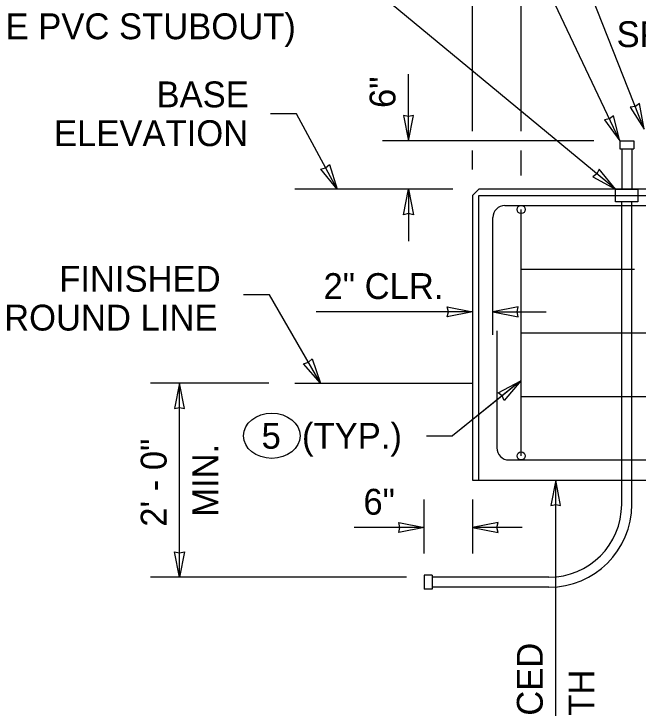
# Model space of a CAD drawing. Extents: x 99888 to 103177, y 100000 to 102076.
# Drawn here: x 101256.4 to 101642.5, y 100934.2 to 101363.8 of the extents above; entities that cross this region are included whole.
import ezdxf

# ---------------------------------------------------------------- set-up
doc = ezdxf.new("R2010")
doc.units = 0
for name, color, linetype in [('Level 10', 7, 'Continuous'), ('Level 15', 7, 'Continuous'), ('Level 2', 7, 'Continuous'), ('Level 20', 7, 'Continuous'), ('Level 36', 7, 'Continuous'), ('Level 6', 7, 'Continuous')]:
    doc.layers.add(name, color=color, linetype=linetype)

msp = doc.modelspace()

# ---------------------------------------------------------------- linework, layer by layer
at = {"layer": 'Level 10'}
for p, q in [((101560.13, 101245.28), (102060.17, 101245.28)), ((101560.13, 101245.28), (102060.17, 101245.28)), ((101570.13, 101090.28), (101570.13, 101242.78)), ((101552.63, 101165.3), (101552.63, 101237.78)), ((101570.13, 101205.9), (101640.13, 101205.9)), ((101570.13, 101205.9), (101640.13, 101205.9)), ((101555.13, 101167.78), (101555.13, 101095.28)), ((101570.13, 101166.53), (101750.13, 101166.53)), ((101570.13, 101127.15), (101750.13, 101127.15)), ((101562.63, 101087.78), (102057.67, 101087.78))]:
    msp.add_line(p, q, dxfattribs=at)
for centre, start, end in [((101560.13, 101237.78), 90, 180), ((101560.13, 101237.78), 90, 180), ((101562.63, 101095.28), 180, 270), ((101562.63, 101095.28), 180, 270)]:
    msp.add_arc(centre, 7.5, start, end, dxfattribs=at)
at = {"layer": 'Level 15'}
for p, q in [((101646.23, 101292.52), (101519.17, 101615.06)), ((101631.06, 101285.28), (101519.17, 101521.98)), ((101628.49, 101255.3), (101463.21, 101392.16)), ((101540.13, 101330.19), (101540.13, 101383.28)), ((101570.13, 101350.07), (101570.13, 101383.28)), ((101570.13, 101306.8), (101570.13, 101350.07)), ((101570.13, 101306.8), (101570.13, 101350.07)), ((101540.13, 101291.28), (101540.13, 101332.3)), ((101500.4, 101285.28), (101500.4, 101326.59)), ((101500.4, 101285.28), (101500.4, 101326.59)), ((101540.13, 101291.28), (101540.13, 101318.19)), ((101570.13, 101291.28), (101570.13, 101306.8)), ((101431.2, 101302.02), (101415.2, 101302.02)), ((101456.33, 101255.28), (101431.2, 101302.02)), ((101570.13, 101291.28), (101570.13, 101294.8)), ((101582.35, 101285.28), (101484.4, 101285.28)), ((101582.35, 101285.28), (101484.4, 101285.28)), ((101615.06, 101285.28), (101582.35, 101285.28)), ((101615.06, 101285.28), (101597.74, 101285.28)), ((101540.13, 101267.53), (101540.13, 101279.28)), ((101540.13, 101267.53), (101540.13, 101279.28)), ((101570.13, 101263.78), (101570.13, 101279.28)), ((101570.13, 101263.78), (101570.13, 101279.28)), ((101527.88, 101255.28), (101430.09, 101255.28)), ((101527.88, 101255.28), (101430.09, 101255.28)), ((101500.4, 101255.28), (101500.4, 101223.28)), ((101500.4, 101255.28), (101500.4, 101223.28)), ((101414.46, 101189.97), (101398.46, 101189.97)), ((101414.46, 101189.97), (101398.46, 101189.97)), ((101446.09, 101135.28), (101414.46, 101189.97)), ((101446.09, 101135.28), (101414.46, 101189.97)), ((101540.13, 101179.4), (101443.35, 101179.4)), ((101540.13, 101179.4), (101443.35, 101179.4)), ((101552.6, 101179.4), (101579.27, 101179.4)), ((101552.6, 101179.4), (101585.56, 101179.4)), ((101570, 101136.86), (101527.57, 101102.75)), ((101414.09, 101135.28), (101340.87, 101135.28)), ((101358.87, 101015.28), (101358.87, 101135.28)), ((101358.87, 101015.28), (101358.87, 101135.28)), ((101430.09, 101135.28), (101540.13, 101135.28)), ((101430.09, 101135.28), (101540.13, 101135.28)), ((101568.5, 101135.65), (101527.57, 101102.75)), ((101511.57, 101102.75), (101527.57, 101102.75)), ((101511.57, 101102.75), (101527.57, 101102.75)), ((101591.47, 100563.54), (101591.47, 101075.28)), ((101591.47, 100563.54), (101591.47, 101075.28)), ((101510.13, 101029.86), (101510.13, 101063.28)), ((101510.13, 101029.86), (101510.13, 101063.28)), ((101540.13, 101063.28), (101540.13, 101029.94)), ((101540.13, 101063.28), (101540.13, 101029.94)), ((101510.13, 101045.94), (101466.8, 101045.94)), ((101510.13, 101045.94), (101466.8, 101045.94)), ((101566.8, 101045.94), (101540.13, 101045.94)), ((101570.66, 101045.94), (101540.13, 101045.94)), ((101499.13, 101015.28), (101340.87, 101015.28))]:
    msp.add_line(p, q, dxfattribs=at)
for points in [[(101646.23, 101292.52), (101643.38, 101308.29), (101640.77, 101306.49), (101637.64, 101306.04)], [(101500.4, 101285.28), (101503.48, 101301), (101500.4, 101300.27), (101497.31, 101301)], [(101500.4, 101285.28), (101503.48, 101301), (101500.4, 101300.27), (101497.31, 101301)], [(101631.06, 101285.28), (101627.25, 101300.84), (101624.76, 101298.88), (101621.65, 101298.25)], [(101456.33, 101255.28), (101446.15, 101267.65), (101449.21, 101268.48), (101451.58, 101270.58)], [(101628.49, 101255.3), (101618.35, 101267.71), (101616.94, 101264.87), (101614.41, 101262.96)], [(101500.4, 101255.28), (101503.48, 101239.55), (101500.4, 101240.28), (101497.31, 101239.55)], [(101500.4, 101255.28), (101503.48, 101239.55), (101500.4, 101240.28), (101497.31, 101239.55)], [(101540.13, 101179.4), (101524.41, 101176.32), (101525.14, 101179.4), (101524.41, 101182.49)], [(101540.13, 101179.4), (101524.41, 101176.32), (101525.14, 101179.4), (101524.41, 101182.49)], [(101552.6, 101179.4), (101568.33, 101176.32), (101567.6, 101179.4), (101568.33, 101182.49)], [(101552.6, 101179.4), (101568.33, 101176.32), (101567.6, 101179.4), (101568.33, 101182.49)], [(101446.09, 101135.28), (101435.55, 101147.35), (101438.59, 101148.26), (101440.9, 101150.44)], [(101570, 101136.86), (101559.68, 101124.61), (101558.31, 101127.47), (101555.81, 101129.42)], [(101358.87, 101135.28), (101355.79, 101119.55), (101358.87, 101120.28), (101361.95, 101119.55)], [(101358.87, 101135.28), (101355.79, 101119.55), (101358.87, 101120.28), (101361.95, 101119.55)], [(101591.47, 101075.28), (101588.38, 101059.55), (101591.47, 101060.28), (101594.55, 101059.55)], [(101591.47, 101075.28), (101588.38, 101059.55), (101591.47, 101060.28), (101594.55, 101059.55)], [(101510.13, 101045.94), (101494.41, 101042.86), (101495.14, 101045.94), (101494.41, 101049.03)], [(101510.13, 101045.94), (101494.41, 101042.86), (101495.14, 101045.94), (101494.41, 101049.03)], [(101540.13, 101045.94), (101555.86, 101042.86), (101555.13, 101045.94), (101555.86, 101049.03)], [(101540.13, 101045.94), (101555.86, 101042.86), (101555.13, 101045.94), (101555.86, 101049.03)], [(101358.87, 101015.28), (101355.79, 101031), (101358.87, 101030.27), (101361.95, 101031)]]:
    msp.add_lwpolyline(points, close=True, dxfattribs=at)
at = {"layer": 'Level 2'}
for p, q in [((101543.88, 101255.28), (101540.13, 101251.53)), ((101543.88, 101255.28), (101540.13, 101251.53)), ((102076.38, 101255.28), (101543.88, 101255.28)), ((101540.13, 101251.53), (101540.13, 101075.28)), ((101543.88, 101075.28), (101543.88, 101251.53)), ((101543.88, 101251.53), (102076.38, 101251.53)), ((101543.88, 101075.28), (101543.88, 101251.53)), ((101543.88, 101251.53), (102076.38, 101251.53)), ((101540.13, 101075.28), (101720.13, 101075.28))]:
    msp.add_line(p, q, dxfattribs=at)
at = {"layer": 'Level 20'}
msp.add_ellipse((101415.89, 101102.76), major_axis=(-17.5, 0), ratio=0.8, dxfattribs=at)
at = {"layer": 'Level 36'}
for centre in [(101570.13, 101242.78), (101570.13, 101242.78), (101570.13, 101090.28), (101570.13, 101090.28)]:
    msp.add_circle(centre, 2.5, dxfattribs=at)
at = {"layer": 'Level 6'}
for p, q in [((101631.06, 101285.28), (101639.81, 101285.28)), ((101631.06, 101285.28), (101631.06, 101280.28)), ((101631.06, 101285.28), (101639.81, 101285.28)), ((101631.06, 101285.28), (101631.06, 101280.28)), ((101639.81, 101285.28), (101639.81, 101280.28)), ((101639.81, 101285.28), (101639.81, 101280.28)), ((101631.06, 101280.28), (101639.81, 101280.28)), ((101631.06, 101280.28), (101639.81, 101280.28)), ((101632.31, 101280.28), (101632.31, 101255.28)), ((101632.31, 101280.28), (101632.31, 101255.28)), ((101638.56, 101280.28), (101638.56, 101255.28)), ((101638.56, 101280.28), (101638.56, 101255.28)), ((101632.31, 101075.28), (101632.31, 101247.56)), ((101632.31, 101075.28), (101632.31, 101247.56)), ((101638.56, 101075.28), (101638.56, 101247.56)), ((101638.56, 101075.28), (101638.56, 101247.56)), ((101632.31, 101060.28), (101632.31, 101075.28)), ((101632.31, 101060.28), (101632.31, 101075.28)), ((101638.56, 101060.28), (101638.56, 101075.28)), ((101638.56, 101060.28), (101638.56, 101075.28)), ((101510.13, 101016.53), (101510.13, 101007.78)), ((101515.13, 101016.53), (101510.13, 101016.53)), ((101510.13, 101016.53), (101510.13, 101007.78)), ((101515.13, 101016.53), (101510.13, 101016.53)), ((101515.13, 101016.53), (101515.13, 101007.78)), ((101515.13, 101016.53), (101515.13, 101007.78)), ((101587.31, 101015.28), (101515.13, 101015.28)), ((101587.31, 101015.28), (101515.13, 101015.28)), ((101515.13, 101007.78), (101510.13, 101007.78)), ((101515.13, 101007.78), (101510.13, 101007.78)), ((101587.31, 101009.03), (101515.13, 101009.03)), ((101587.31, 101009.03), (101515.13, 101009.03))]:
    msp.add_line(p, q, dxfattribs=at)
msp.add_lwpolyline([(101628.49, 101255.3), (101642.34, 101255.3), (101642.34, 101247.56), (101628.49, 101247.56)], close=True, dxfattribs=at)
msp.add_lwpolyline([(101628.49, 101255.3), (101642.34, 101255.3), (101642.34, 101247.56), (101628.49, 101247.56)], close=True, dxfattribs=at)
for radius in [45, 51.25, 45, 51.25]:
    msp.add_arc((101587.31, 101060.28), radius, 270, 0, dxfattribs=at)

# ---------------------------------------------------------------- texts
at = {"layer": 'Level 20'}
for s, p in [('GLUE PVC STUBOUT)', (101207.3, 101348.16)), ('SPACES', (101629.13, 101343.28)), ('5', (101409.58, 101094.76)), ('6"', (101472.57, 101053.94))]:
    msp.add_text(s, height=16, dxfattribs=at).set_placement(p)
for s, rotation, p in [('BASE', 360, (101344.63, 101306.02)), ('6"', 90, (101492.4, 101305.6)), ('6"', 90, (101492.4, 101305.6)), ('ELEVATION', 360, (101281.22, 101282.02)), ('FINISHED', 360, (101284.44, 101191.89)), ('2" CLR.', 360, (101447.89, 101187.4)), ('GROUND LINE', 360, (101233.73, 101167.89)), ('(TYP.)', 360, (101434.59, 101094.75)), ('2\' - 0"', 90, (101350.87, 101046.49)), ('MIN.', 90, (101382.87, 101052.64)), ('CONCRETE SHALL BE PLACED', 90, (101583.47, 100654.88)), ('DIRECTLY AGAINST EARTH', 90, (101615.47, 100673.91))]:
    msp.add_text(s, height=16, rotation=rotation, dxfattribs=at).set_placement(p)

doc.saveas('drawing.dxf')
